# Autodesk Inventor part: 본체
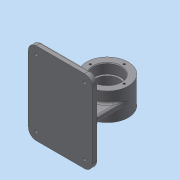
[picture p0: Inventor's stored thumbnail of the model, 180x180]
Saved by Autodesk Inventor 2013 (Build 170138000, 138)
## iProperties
Created: 2019-09
Part Number: 본체
Material: 일반
Document SubType Name: Modeling
Designer: Administrator
Density: 1 g/cm^3
Author: Administrator
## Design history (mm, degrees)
sketch "스케치2"
  geometry: C1 r 32 at (0, 0); 1 further point
  constraints: 1 centre point, 1 coincident
  dimensions: "d0" = 64 diameter of C1
extrude "돌출1" new body sketch "스케치2" stored distance "d2" = 42; taper "d3" = 0 deg
sketch "스케치3"
  geometry: C1 r 32 at (0, 0) reference; C2 r 21 at (0, 0)
  constraints: 1 centre point, 1 coincident
  dimensions: "d4" = 42 diameter of C2
extrude "돌출2" cut sketch "스케치3" distance "d5" = 15; taper "d6" = 0 deg
sketch "스케치4"
  geometry: C1 r 21 at (0, 0) reference; C2 r 18 at (0, 0)
  constraints: 1 centre point, 1 coincident
  dimensions: "d7" = 36 diameter of C2
extrude "돌출3" cut sketch "스케치4" distance "d8" = 6; taper "d9" = 0 deg
node "작업 평면1"
sketch "스케치9"
  geometry: L1 (62, 63)-(-36, 63); L2 (-36, 63)-(-36, -63); L3 (-36, -63)-(62, -63); L4 (62, -63)-(62, 63); 1 further point
  constraints: 8 end point, 2 parallel, 1 horizontal, 1 perpendicular
  dimensions: "d28" = 98 distance of L2.end L3.end; "d30" = 126 distance of L1.end L2.end; "d31" = 63 distance from line of point (0, 0) L3; "d32" = 62 distance from line of point (0, 0) L4
extrude "돌출8" join sketch "스케치9" distance "d33" = 9; taper "d34" = 0 deg
sketch "스케치10"
  geometry: L1 (32, -4)-(-32, -4); L2 (-32, -4)-(-32, 4); L3 (-32, 4)-(32, 4); L4 (32, 4)-(32, -4); L5 (32, -4)-(-32, 4); L6 (-32, -4)-(32, 4); L7 (-4, -17)-(4, -17); L8 (4, -17)-(4, 17); L9 (4, 17)-(-4, 17); L10 (-4, 17)-(-4, -17); L11 (-4, -17)-(4, 17); L12 (4, -17)-(-4, 17); 1 further point
  constraints: 24 end point, 4 midpoint, 4 parallel, 2 horizontal, 2 perpendicular
  dimensions: "d35" = 64 distance of L2.end L3.end; "d36" = 8 distance of L1.end L2.end; "d37" = 8 distance of L9.end L8.end; "d38" = 34 distance of L8.end L7.end
extrude "돌출9" join sketch "스케치10" stored distance "d39" = 9; taper "d40" = 0 deg
fillet "모깎기1" dims "d41" = 12
sketch "스케치11" dims "d44" = 52
  geometry: L1 (-24, -59)-(50, -59) reference; C1 r 32 at (0, 0) reference; 2 further points
  constraints: 1 coincident, 1 horizontal alignment, 2 other
  dimensions: "d43" = 59 distance from line of L1 point (-26, 0)
hole "구멍1" sketch "스케치11" at (-26, 0) diameter "d45" = 3.242; stored, may be unused: countersink angle "d49" = 90 deg, drill point angle "d51" = 118 deg; dims "d46" = 8, "d47" = 4, "d48" = 2, "d50" = 10
sketch "스케치12"
  geometry: A1 r 12 centre (-50, 51) between (-50, 63) and (-62, 51) reference; A2 r 12 centre (24, 51) between (36, 51) and (24, 63) reference; 3 further points
  constraints: 2 coincident
hole "구멍2" sketch "스케치12" at (-50, 51), (24, 51) diameter "d58" = 4.5; stored, may be unused: countersink angle "d62" = 90 deg, drill point angle "d64" = 118 deg; dims "d59" = 8, "d60" = 8, "d61" = 4.4, "d63" = 10
fillet "모깎기2" dims "d68" = 0.3
chamfer "모따기1" distance "d69" = 1; stored, may be unused: second distance "d70" = 2, angle "d71" = 45 deg
fillet "모깎기3" dims "d72" = 3
fillet "모깎기4" dims "d73" = 3
fillet "모깎기5" dims "d74" = 3
fillet "모깎기6" dims "d75" = 3
sketch "스케치13"
  geometry: L1 (-59, -51)-(-59, 51) reference; L2 (24, 63)-(-50, 63) reference; 2 further points
  constraints: 1 other
  dimensions: "d76" = 63 distance from line of L2 point (-49, 0); "d77" = 10 distance from line of L1 point (-49, 0)
feature "엠보싱1" sketch "스케치13" dims "d28" = 98, "d30" = 126, "d31" = 63, "d32" = 62, "d78" = 0.5, "d79" = 0
node "솔리드1"
mirror "대칭1"
pattern_circular "원형 패턴1" dims angle "d53" = 360 deg
mirror "대칭2"
pattern_linear "직사각형 패턴1" dims "d67" = 102
other parameters: "d12" = -59
